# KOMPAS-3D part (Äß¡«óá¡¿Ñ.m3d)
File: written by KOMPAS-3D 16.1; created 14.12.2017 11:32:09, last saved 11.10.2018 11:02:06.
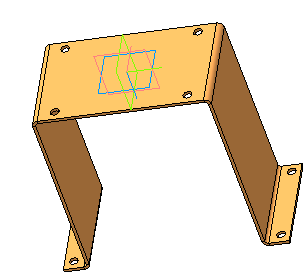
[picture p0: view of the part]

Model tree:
1. Эскиз:1
2. Листовое тело:1
     Расстояние 1 = 10; Расстояние 2 = 10; Толщина листового тела = 3; Радиус сгиба = 5
3. Сгиб:1
     Радиус сгиба = 3; Коэффициент = 0.4; Величина сгиба = 10; Толщина листового тела = 3; Ширина освобождения сгиба = 3; Ширина сгиба = 104; Длина 1 = 192; Длина 2 = 10
4. Сгиб:2
     Радиус сгиба = 3; Коэффициент = 0.4; Величина сгиба = 10; Толщина листового тела = 3; Ширина освобождения сгиба = 3; Ширина сгиба = 104; Длина 1 = 192; Длина 2 = 10
5. Сгиб:3
6. Сгиб(1) - Сгиб:3
     Радиус сгиба = 3; Коэффициент = 0.4; Величина сгиба = 10; Коэффициент = -3.29006e-05; Ширина освобождения сгиба = 3; Ширина сгиба = 104; Длина 1 = 26; Длина 2 = 10
7. Сгиб:4
8. Сгиб(1) - Сгиб:4
     Радиус сгиба = 3; Коэффициент = 0.4; Величина сгиба = 10; Угол сгиба = -141323; Ширина освобождения сгиба = 3; Ширина сгиба = 104; Длина 1 = 26; Длина 2 = 10
9. Эскиз:9
10. Вырез в листовом теле:1
     Расстояние 1 = 10; Глубина выреза = 10
11. Эскиз:10
12. Вырез в листовом теле:2  (labels: ASTRA-302-1 выставка; Сталь 08  ГОСТ 1050-2013)
     Расстояние 1 = 10; Глубина выреза = 10

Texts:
  Body Specification ( left align )
  Body Specificaton ( centered )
